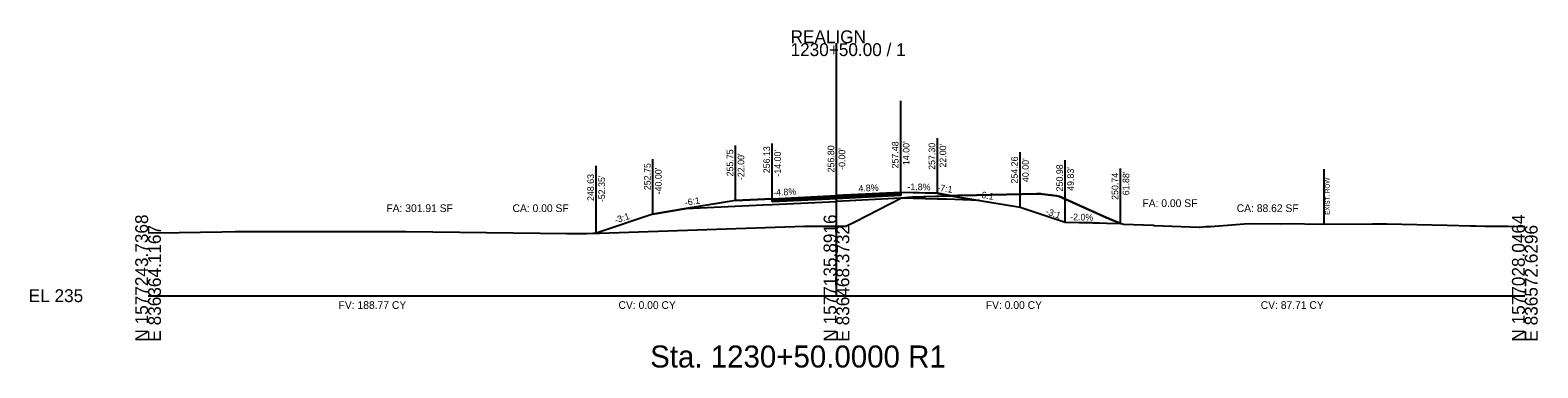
# Model space of a CAD drawing. Extents: x -26 to 6303, y -16 to 9563.
# Drawn here: x -25.7 to 302.8, y 9484.3 to 9557.8 of the extents above; entities that cross this region are included whole.
import ezdxf

# ---------------------------------------------------------------- set-up
doc = ezdxf.new("R2010")
doc.units = 0
for name, color, linetype in [('ASPHALT_19MM1', 7, 'Continuous'), ('ASPHALT_9_5MM1', 7, 'Continuous'), ('CONST_DCH', 7, 'Continuous'), ('CONST_LV3', 7, 'Continuous'), ('Draft_XS_Grid', 7, 'Continuous'), ('Draft_XS_Text', 7, 'Continuous'), ('DTM_TEMP_DROP', 7, 'Continuous'), ('DTM_X_GROUND', 7, 'Continuous'), ('X_PROFILES_1', 7, 'Continuous'), ('X_TRANS_EOP', 7, 'Continuous'), ('XS_CELL', 7, 'Continuous'), ('XS_M_SHAPES_EARTHWORK', 7, 'Continuous'), ('XS_P_ASPHALT', 7, 'Continuous'), ('XS_P_DR_ASPHALT', 7, 'Continuous'), ('XS_P_GROUND', 7, 'Continuous'), ('XS_P_SHOULDER', 7, 'Continuous'), ('XS_P_SUBGRADE_GRANULAR', 7, 'Continuous'), ('XS_P_TX_CLEARZONE', 7, 'Continuous'), ('XS_P_TX_FS_BS', 7, 'Continuous'), ('XS_PLAN_CLEAR_ZONE', 7, 'Continuous'), ('XS_SHEET_EW_TX_AREA', 7, 'Continuous'), ('XS_SHEET_EW_TX_VOLUME', 7, 'Continuous'), ('XS_X_ROW', 7, 'Continuous')]:
    doc.layers.add(name, color=color, linetype=linetype)

msp = doc.modelspace()

# ---------------------------------------------------------------- linework, layer by layer
at = {"layer": 'ASPHALT_19MM1'}
msp.add_lwpolyline([(136, 9520.8), (136, 9520.53), (150, 9521.2), (150, 9521.2), (164, 9521.87), (164, 9521.87), (164, 9522.14), (164, 9522.14), (164, 9522.14), (150, 9521.47), (150, 9521.47), (136, 9520.8), (136, 9520.8)], dxfattribs=at)
at = {"layer": 'ASPHALT_9_5MM1'}
msp.add_lwpolyline([(136, 9521.13), (150, 9521.8), (150, 9521.8), (164, 9522.48), (164, 9522.48), (164, 9522.35), (164, 9522.35), (150, 9521.68), (150, 9521.68), (136, 9521.01), (136, 9521.13)], dxfattribs=at)
at = {"layer": 'CONST_LV3'}
for points in [[(164, 9522.45), (164, 9522.45), (150, 9521.8)], [(172, 9522.26), (164, 9522.45), (164, 9522.45)], [(110, 9517.75), (117.29, 9518.96), (117.29, 9518.96)]]:
    msp.add_lwpolyline(points, dxfattribs=at)
at = {"layer": 'DTM_X_GROUND'}
msp.add_lwpolyline([(0, 9513.77), (0.27, 9513.76), (2.14, 9513.72), (16.11, 9513.9), (19, 9514.01), (42.51, 9513.99), (48.7, 9514.01), (51.95, 9514), (56.22, 9513.98), (91.24, 9513.57), (92.44, 9513.57), (93.66, 9513.57), (94.89, 9513.56), (95.61, 9513.58), (96.94, 9513.61), (98.34, 9513.65), (143.04, 9515.17), (150.63, 9515.14), (151.2, 9515.15), (152.06, 9515.13), (154.17, 9516.19), (164.21, 9521.3), (165.65, 9521.46), (166.61, 9521.57), (176.48, 9521.8), (180.54, 9521.89), (193.66, 9522.16), (194.51, 9522.18), (194.96, 9522.12), (197.95, 9521.73), (198.59, 9521.61), (208.78, 9517.01), (211.74, 9515.77), (212.03, 9515.71), (212.54, 9515.59), (219.07, 9515.33), (219.23, 9515.32), (229.02, 9514.94), (229.17, 9514.93), (229.18, 9514.93), (230.51, 9515.06), (231.51, 9515.09), (239.79, 9515.7), (246.79, 9515.62), (248.58, 9515.69), (255.48, 9515.58), (266.83, 9515.66), (269.92, 9515.68), (283.11, 9515.34), (288.21, 9515.21), (289.3, 9515.19), (291.28, 9515.17), (292.54, 9515.17), (296.37, 9515.14), (300, 9515.09)], dxfattribs=at)
at = {"layer": 'X_TRANS_EOP'}
msp.add_line((164, 9522.45), (164, 9542.45), dxfattribs=at)
at = {"layer": 'XS_CELL'}
for p, q in [((150, 9500), (150, 9555)), ((0, 9500), (150, 9500)), ((150, 9500), (300, 9500))]:
    msp.add_line(p, q, dxfattribs=at)
at = {"layer": 'XS_M_SHAPES_EARTHWORK'}
msp.add_lwpolyline([(97.65, 9513.63), (98.34, 9513.65), (143.04, 9515.17), (150.63, 9515.14), (151.2, 9515.15), (152.06, 9515.13), (154.17, 9516.19), (164.21, 9521.3), (165.65, 9521.46), (166.61, 9521.57), (175.18, 9521.77), (172, 9522.3), (164, 9522.48), (164, 9522.35), (164, 9522.14), (164, 9521.87), (150, 9521.2), (136, 9520.53), (136, 9520.8), (136, 9521.01), (136, 9521.13), (128, 9520.75), (117.29, 9518.96), (110, 9517.75)], close=True, dxfattribs=at)
at = {"layer": 'XS_P_GROUND'}
for points in [[(175.18, 9521.77), (175.18, 9521.77), (172, 9522.3)], [(172, 9522.26), (190, 9519.26), (199.83, 9515.98)], [(128, 9520.75), (110, 9517.75), (97.65, 9513.63)], [(199.83, 9515.98), (211.89, 9515.74)]]:
    msp.add_lwpolyline(points, dxfattribs=at)
at = {"layer": 'XS_P_SHOULDER'}
for points in [[(128, 9520.75), (136, 9521.13), (136, 9521.13)], [(172, 9522.3), (164, 9522.48), (164, 9522.48)]]:
    msp.add_lwpolyline(points, dxfattribs=at)
at = {"layer": 'XS_P_SUBGRADE_GRANULAR'}
for points in [[(164, 9521.21), (164, 9521.21), (150, 9520.53)], [(172, 9520.99), (172, 9520.99), (172, 9520.99), (164, 9521.21)], [(181.08, 9520.75), (174, 9521.03), (174, 9521.03), (174, 9521.03), (172, 9520.99)], [(117.29, 9518.96), (134, 9519.77), (134, 9519.77), (136, 9519.86), (136, 9519.86)], [(136, 9519.86), (150, 9520.53), (150, 9520.53)]]:
    msp.add_lwpolyline(points, dxfattribs=at)
at = {"layer": 'XS_P_TX_CLEARZONE'}
for p, q in [((164, 9522.48), (164, 9534.48)), ((172, 9522.3), (172, 9534.3)), ((128, 9520.75), (128, 9532.75)), ((136, 9521.13), (136, 9533.13)), ((150, 9521.8), (150, 9533.8)), ((190, 9519.26), (190, 9531.26)), ((97.65, 9513.63), (97.65, 9528.32)), ((110, 9517.75), (110, 9529.75)), ((199.83, 9515.98), (199.83, 9529.52)), ((211.89, 9515.74), (211.89, 9527.74))]:
    msp.add_line(p, q, dxfattribs=at)
at = {"layer": 'XS_P_TX_FS_BS'}
for p, q in [((174.95, 9521.77), (190, 9519.26)), ((190, 9519.26), (199.83, 9515.98)), ((199.83, 9515.98), (205.75, 9515.93))]:
    msp.add_line(p, q, dxfattribs=at)
msp.add_lwpolyline([(205.75, 9515.93), (208.86, 9515.83), (211.89, 9515.74), (208.78, 9517.01), (198.59, 9521.61), (197.95, 9521.73), (194.96, 9522.12), (194.51, 9522.18), (193.66, 9522.16), (180.54, 9521.89), (176.48, 9521.8), (174.95, 9521.77)], dxfattribs=at)
at = {"layer": 'XS_PLAN_CLEAR_ZONE'}
msp.add_lwpolyline([(136, 9521.01), (136, 9520.8), (150, 9521.47), (150, 9521.47), (164, 9522.14), (164, 9522.14), (164, 9522.35), (164, 9522.35), (164, 9522.35), (150, 9521.68), (150, 9521.68), (136, 9521.01), (136, 9521.01)], dxfattribs=at)
at = {"layer": 'XS_X_ROW'}
msp.add_line((256.26, 9515.59), (256.26, 9527.59), dxfattribs=at)

# ---------------------------------------------------------------- texts
at = {"layer": 'CONST_DCH'}
for p in [(135.92, 9521.01), (149.92, 9521.68), (163.92, 9522.36)]:
    msp.add_text('X', height=0.24, dxfattribs=at).set_placement(p)
at = {"layer": 'Draft_XS_Grid'}
msp.add_text('-', height=0.0001, dxfattribs=at).set_placement((0, 9500))
at = {"layer": 'Draft_XS_Text'}
msp.add_text('Sta. 1230+50.0000 R1', height=4.8, dxfattribs=at).set_placement((109.41, 9484.35))
at = {"layer": 'DTM_TEMP_DROP'}
for p in [(171.92, 9522.14), (175.1, 9521.65), (97.57, 9513.51)]:
    msp.add_text('X', height=0.24, dxfattribs=at).set_placement(p)
at = {"layer": 'X_PROFILES_1'}
for p in [(171.92, 9522.14), (189.92, 9519.14)]:
    msp.add_text('X', height=0.24, dxfattribs=at).set_placement(p)
at = {"layer": 'XS_CELL'}
for s, p in [('REALIGN', (140, 9555)), ('1230+50.00 / 1', (140, 9552.2)), ('EL 235', (-26, 9498.6))]:
    msp.add_text(s, height=2.8, dxfattribs=at).set_placement(p)
for s, p in [('N 1577243.7368', (0, 9490)), ('E 836364.1167', (2.8, 9490)), ('N 1577135.8916', (150, 9490)), ('E 836468.3732', (152.8, 9490)), ('N 1577028.0464', (300, 9490)), ('E 836572.6296', (302.8, 9490))]:
    msp.add_text(s, height=2.8, rotation=90, dxfattribs=at).set_placement(p)
at = {"layer": 'XS_P_ASPHALT'}
msp.add_text('X', height=0.24, dxfattribs=at).set_placement((202.7, 9514.88))
at = {"layer": 'XS_P_DR_ASPHALT'}
msp.add_text('X', height=0.24, dxfattribs=at).set_placement((109.92, 9517.63))
at = {"layer": 'XS_P_SHOULDER'}
for p in [(171.92, 9522.18), (127.92, 9520.63)]:
    msp.add_text('X', height=0.24, dxfattribs=at).set_placement(p)
at = {"layer": 'XS_P_SUBGRADE_GRANULAR'}
for p in [(175.1, 9521.65), (97.57, 9513.51)]:
    msp.add_text('X', height=0.24, dxfattribs=at).set_placement(p)
at = {"layer": 'XS_P_TX_CLEARZONE'}
for s, p in [('255.75', (127.52, 9525.99)), ("-22.00'", (129.92, 9525.18)), ('256.13', (135.52, 9526.67)), ("-14.00'", (137.92, 9525.93)), ('256.80', (149.52, 9526.86)), ("-0.00'", (151.92, 9527.41)), ('257.48', (163.52, 9527.72)), ("14.00'", (165.92, 9528.45)), ('257.30', (171.52, 9527.42)), ("22.00'", (173.92, 9527.91)), ('252.75', (109.52, 9522.99)), ("-40.00'", (111.92, 9522.06)), ('254.26', (189.52, 9524.42)), ("40.00'", (191.92, 9524.75)), ('250.98', (199.35, 9522.72)), ("49.83'", (201.75, 9522.84)), ('248.63', (97.17, 9520.62)), ("-52.35'", (99.57, 9520.37)), ('250.74', (211.41, 9520.87)), ("61.88'", (213.81, 9521.87))]:
    msp.add_text(s, height=1.44, rotation=90, dxfattribs=at).set_placement(p)
at = {"layer": 'XS_P_TX_FS_BS'}
for s, rotation, p in [('4.8%', 2.7481, (154.83, 9522.64)), ('-1.8%', 358.9549, (165.46, 9523.02)), ('-7:1', 351.2946, (171.89, 9522.88)), ('-6:1', 9.4642, (117.08, 9519.54)), ('-4.8%', 2.7481, (136.24, 9521.75)), ('-6:1', 350.3755, (180.87, 9521.41)), ('-3:1', 18.4332, (101.92, 9515.69)), ('-3:1', 341.5651, (195.45, 9517.78)), ('-2.0%', 358.8542, (200.92, 9516.44))]:
    msp.add_text(s, height=1.44, rotation=rotation, dxfattribs=at).set_placement(p)
at = {"layer": 'XS_SHEET_EW_TX_AREA'}
for s, p in [('FA: 0.00 SF', (216.67, 9519.32)), ('FA: 301.91 SF', (51.93, 9518.22)), ('CA: 0.00 SF', (79.42, 9518.22)), ('CA: 88.62 SF', (237.23, 9518.22))]:
    msp.add_text(s, height=1.68, dxfattribs=at).set_placement(p)
at = {"layer": 'XS_SHEET_EW_TX_VOLUME'}
for s, p in [('FV: 188.77 CY', (41.52, 9497.12)), ('CV: 0.00 CY', (102.51, 9497.12)), ('FV: 0.00 CY', (182.55, 9497.12)), ('CV: 87.71 CY', (242.45, 9497.12))]:
    msp.add_text(s, height=1.68, dxfattribs=at).set_placement(p)
at = {"layer": 'XS_X_ROW'}
msp.add_text('EXIST. ROW', height=1, rotation=90, dxfattribs=at).set_placement((257.46, 9517.59))

doc.saveas('drawing.dxf')
